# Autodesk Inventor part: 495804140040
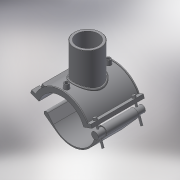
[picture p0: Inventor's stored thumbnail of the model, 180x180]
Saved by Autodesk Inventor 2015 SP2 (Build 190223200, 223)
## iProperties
Created: 2017-07
Part Number: 495804140040
Material: Generic
Description: PLASSON BRANCH SADDLE 140-40
Document SubType Name: Modeling
Designer: KIM
Density: 1 g/cm^3
Appearance: Default
Author: KIM
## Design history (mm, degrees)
derived "495804.ipt"
feature "Solid1::495804.ipt"
feature "Solid2::495804.ipt"
tag "TaggingFeature1"
body "Solid1"
body "Solid2"
other parameters: "d3" = 35, "d4" = 118, "d5" = 0, "d6" = 0.1, "d8" = 0, "d19" = 6, "d20" = 6, "d21" = 70.8, "d23" = 0, "d24" = 35.4, "d26" = 0, "d27" = 3, "d28" = 3, "d29" = 3, "d30" = 46.66667, "d31" = 6, "d32" = 0, "d33" = 0, "d34" = 0.6, "d40" = 83.2, "d41" = 44, "d43" = 0, "d45" = 0, "d47" = 158, "d50" = 0, "d70" = 15, "d72" = 0, "d73" = 6, "d75" = 5, "d76" = 0, "d77" = 7, "d79" = 15, "d80" = 47.2, "d82" = 5 deg, "d84" = 4, "d85" = 14, "d86" = 0, "d87" = 3, "d88" = 0, "d89" = 1, "d90" = 1, "d91" = 94.4, "d92" = 0, "d93" = 0.5, "d94" = 73.68421, "d96" = 163.2, "d97" = 2.36, "d98" = 0, "d102" = 1.2, "d103" = 32, "d105" = 0, "d109" = -26, "d117" = 0.4, "d120" = 140 deg, "d121" = 24.228, "d122" = 20 deg, "d124" = 96, "d126" = 0, "d143" = 147, "d150" = 25.2, "d159" = 4, "d161" = 3.5, "d162" = 70.8, "d163" = 0, "d167" = 28, "d168" = 72.72727, "d173" = 1, "d176" = 20 deg, "d177" = 9.8, "d180" = 0, "d185" = 38.35, "d186" = 38.35, "d188" = 6, "d189" = 9.8, "d190" = 0, "d202" = 0, "d216" = 106.2, "d217" = 0, "d221" = 43.66, "d222" = 9.8, "d223" = 5.88, "d225" = 5.88, "d227" = 20.16, "d230" = 86.8, "d236" = 20 deg, "d237" = 87, "d238" = 20 deg, "d239" = 9.8, "H_" = 78, "L_" = 118, "d_t" = 6, "H_1" = 68, "d148" = 3.5, "d160" = 3.5
